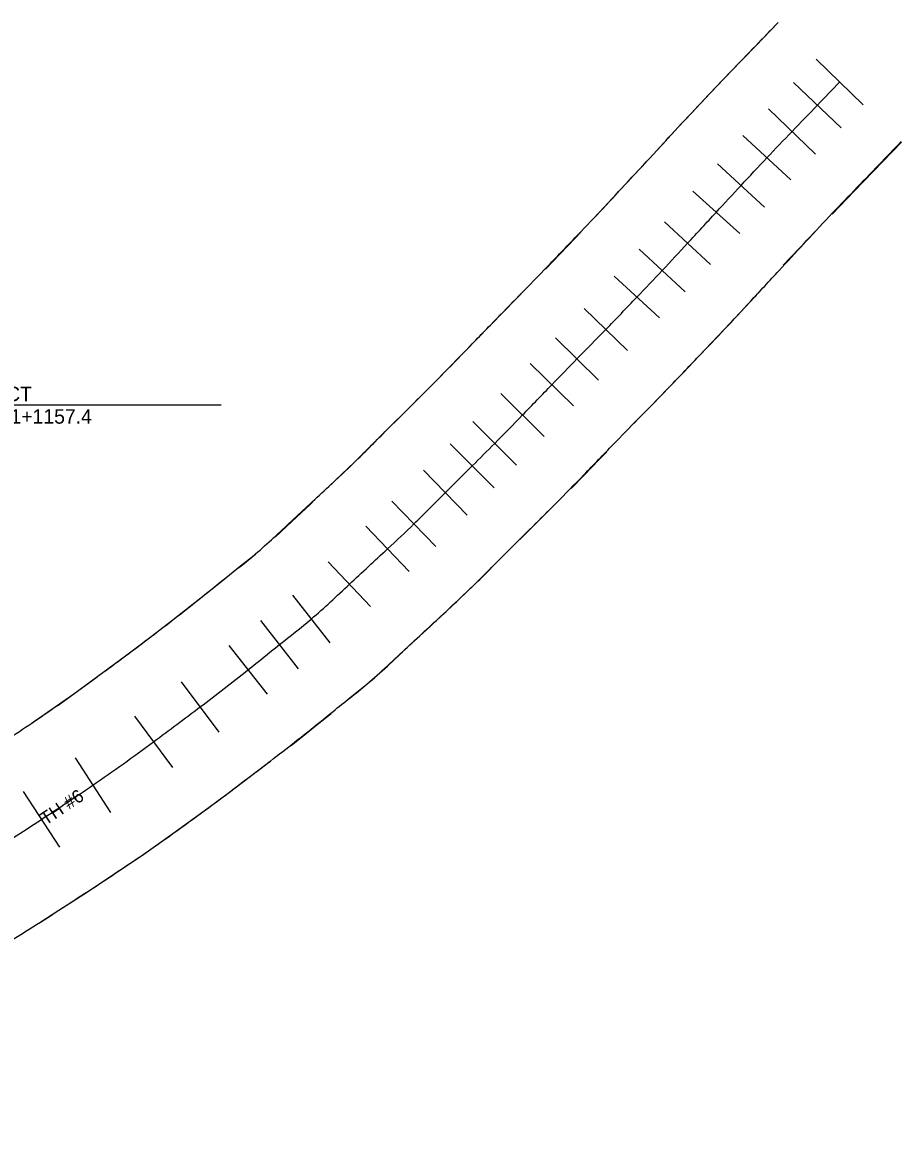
# Model space of a CAD drawing. Extents: x 435838 to 436160, y 121991 to 122158.
# Drawn here: x 436083.1 to 436160.1, y 122055.8 to 122154.8 of the extents above; entities that cross this region are included whole.
import ezdxf

# ---------------------------------------------------------------- set-up
doc = ezdxf.new("R2010")
doc.units = 0
for name, color, linetype in [('Level 1', 7, 'Continuous'), ('Level 10', 7, 'Continuous'), ('Level 12', 7, 'Continuous'), ('Level 5', 7, 'Continuous')]:
    doc.layers.add(name, color=color, linetype=linetype)

msp = doc.modelspace()

# ---------------------------------------------------------------- linework, layer by layer
at = {"layer": 'Level 1'}
for points in [[(436133.379, 122137.953), (436133.694, 122138.283), (436135.881, 122140.633), (436137.129, 122141.978), (436138.377, 122143.324), (436140.557, 122145.686), (436141.711, 122146.929), (436142.871, 122148.165), (436145.11, 122150.508), (436147.344, 122152.824), (436149.292, 122154.844)], [(436154.028, 122138.075), (436155.957, 122140.092), (436160.096, 122144.384)], [(436128.933, 122133.244), (436130.195, 122134.564), (436131.538, 122135.97), (436132.038, 122136.494)], [(436149.745, 122133.599), (436152.527, 122136.507)], [(436109.989, 122114.258), (436112.189, 122116.336), (436113.532, 122117.673), (436114.874, 122119.011), (436117.223, 122121.352), (436119.16, 122123.281), (436120.36, 122124.497), (436121.551, 122125.723), (436122.829, 122127.042), (436124.108, 122128.36), (436126.322, 122130.636), (436127.291, 122131.62)], [(436135.656, 122118.719), (436137.05, 122120.152), (436138.326, 122121.448), (436139.598, 122122.749), (436140.979, 122124.19), (436142.357, 122125.634), (436144.61, 122127.995), (436146.871, 122130.423), (436147.973, 122131.612)], [(436131.173, 122114.046), (436132.322, 122115.229), (436133.608, 122116.557), (436134.302, 122117.273)], [(436105.28, 122109.813), (436106.711, 122111.164), (436108.353, 122112.685), (436108.564, 122112.881)], [(436111.689, 122095.629), (436111.811, 122095.727), (436113.293, 122096.918), (436115.093, 122098.503), (436116.839, 122100.152), (436118.53, 122101.718), (436120.219, 122103.287), (436122.635, 122105.57), (436124.048, 122106.977), (436125.46, 122108.385), (436127.809, 122110.724), (436129.522, 122112.43)], [(436083.974, 122093.536), (436085.033, 122094.249), (436087.623, 122096.066), (436090.18, 122097.927), (436092.163, 122099.399), (436094.134, 122100.887), (436096.194, 122102.461), (436098.234, 122104.061), (436099.584, 122105.145), (436100.934, 122106.23), (436102.234, 122107.274), (436103.524, 122108.311)], [(436106.655, 122091.553), (436107.548, 122092.253), (436108.95, 122093.379), (436110.168, 122094.358)], [(436084.736, 122076.114), (436086.316, 122077.124), (436088.9, 122078.804), (436091.234, 122080.34), (436093.551, 122081.901), (436096.31, 122083.836), (436099.036, 122085.819), (436101.134, 122087.376), (436103.22, 122088.951), (436104.81, 122090.166)]]:
    msp.add_lwpolyline(points, dxfattribs=at)
for points in [[(436028.85, 122070.697), (436032.873, 122071.242), (436037.712, 122072.211), (436044.314, 122073.897), (436048.282, 122075.037), (436051.469, 122076.128), (436054.388, 122077.32), (436057.846, 122078.731), (436060.604, 122079.932), (436063.68, 122081.42), (436067.336, 122083.189), (436071.379, 122085.503), (436075.746, 122088.17), (436080.678, 122091.35), (436085.033, 122094.249), (436090.18, 122097.927), (436094.134, 122100.887), (436098.234, 122104.061), (436100.934, 122106.23), (436103.533, 122108.318), (436106.685, 122111.192), (436109.967, 122114.237), (436112.189, 122116.336), (436114.874, 122119.011), (436117.223, 122121.352), (436119.16, 122123.281), (436121.551, 122125.723), (436124.108, 122128.36), (436126.322, 122130.636), (436128.824, 122133.185), (436131.511, 122135.996), (436133.694, 122138.283), (436135.881, 122140.633), (436138.377, 122143.324), (436140.557, 122145.686), (436142.871, 122148.165), (436145.11, 122150.508), (436147.344, 122152.824), (436149.292, 122154.844)], [(436030.864, 122055.833), (436035.355, 122056.442), (436041.042, 122057.579), (436048.242, 122059.419), (436052.784, 122060.723), (436056.737, 122062.076), (436060.058, 122063.432), (436063.674, 122064.909), (436066.866, 122066.298), (436070.214, 122067.918), (436074.336, 122069.913), (436079.015, 122072.591), (436083.72, 122075.464), (436088.9, 122078.804), (436093.551, 122081.901), (436099.036, 122085.819), (436103.22, 122088.951), (436107.524, 122092.283), (436110.328, 122094.536), (436113.293, 122096.918), (436116.839, 122100.152), (436120.219, 122103.287), (436122.635, 122105.57), (436125.46, 122108.385), (436127.809, 122110.724), (436129.812, 122112.719), (436132.295, 122115.255), (436134.868, 122117.91), (436137.05, 122120.152), (436139.598, 122122.749), (436142.357, 122125.634), (436144.61, 122127.995), (436146.871, 122130.423), (436149.387, 122133.138), (436151.551, 122135.482), (436153.775, 122137.865), (436155.93, 122140.118), (436158.142, 122142.412), (436160.09, 122144.432)]]:
    msp.add_spline(points, degree=3, dxfattribs=at)
at = {"layer": 'Level 10'}
msp.add_line((436100.52, 122121.357), (436063.934, 122121.357), dxfattribs=at)
at = {"layer": 'Level 12'}
for p, q in [((436152.625, 122151.629), (436156.756, 122147.647)), ((436150.663, 122149.593), (436154.823, 122145.643)), ((436148.455, 122147.303), (436152.585, 122143.323)), ((436146.225, 122144.949), (436150.421, 122141.08)), ((436143.993, 122142.484), (436148.114, 122138.683)), ((436141.826, 122140.093), (436145.938, 122136.369)), ((436139.361, 122137.395), (436143.391, 122133.661)), ((436137.14, 122135.002), (436141.163, 122131.275)), ((436134.957, 122132.649), (436138.91, 122128.981)), ((436132.32, 122129.813), (436136.101, 122126.121)), ((436129.796, 122127.238), (436133.575, 122123.549)), ((436127.593, 122124.991), (436131.382, 122121.278)), ((436125.032, 122122.378), (436128.813, 122118.6)), ((436122.57, 122119.914), (436126.401, 122116.085)), ((436120.594, 122117.97), (436124.438, 122114.105)), ((436118.253, 122115.668), (436122.081, 122111.727)), ((436115.48, 122112.941), (436119.343, 122108.965)), ((436113.189, 122110.746), (436116.997, 122106.778)), ((436109.907, 122107.618), (436113.617, 122103.725)), ((436106.769, 122104.698), (436110.056, 122100.538)), ((436103.986, 122102.5), (436107.275, 122098.265)), ((436101.199, 122100.298), (436104.558, 122096.045)), ((436097.038, 122097.133), (436100.315, 122092.705)), ((436092.952, 122094.113), (436096.264, 122089.633)), ((436087.747, 122090.459), (436090.836, 122085.69)), ((436083.207, 122087.517), (436086.37, 122082.636))]:
    msp.add_line(p, q, dxfattribs=at)
msp.add_spline([(436029.857, 122063.265), (436034.114, 122063.842), (436039.377, 122064.895), (436046.278, 122066.658), (436050.533, 122067.88), (436054.103, 122069.102), (436057.223, 122070.376), (436060.76, 122071.82), (436063.735, 122073.115), (436066.947, 122074.669), (436070.836, 122076.551), (436075.197, 122079.047), (436079.733, 122081.817), (436084.789, 122085.077), (436089.292, 122088.075), (436094.608, 122091.873), (436098.677, 122094.919), (436102.879, 122098.172), (436105.631, 122100.383), (436108.413, 122102.618), (436111.762, 122105.672), (436115.093, 122108.762), (436117.412, 122110.953), (436120.167, 122113.698), (436122.516, 122116.038), (436124.486, 122118), (436126.923, 122120.489), (436129.488, 122123.135), (436131.686, 122125.394), (436134.211, 122127.967), (436136.934, 122130.815), (436139.152, 122133.139), (436141.376, 122135.528), (436143.882, 122138.231), (436146.054, 122140.584), (436148.323, 122143.015), (436150.52, 122145.313), (436152.743, 122147.618), (436154.691, 122149.638)], degree=3, dxfattribs=at)

# ---------------------------------------------------------------- texts
at = {"layer": 'Level 10'}
for s, p in [('END R.O.W. PROJECT', (436065.939, 122121.697)), ('BRO 1443 (32) STA. 1+1157.4', (436065.939, 122119.727))]:
    msp.add_text(s, height=1.270002, dxfattribs=at).set_placement(p)
at = {"layer": 'Level 5'}
msp.add_text('TH #6', height=1.142988, rotation=33.99999996, dxfattribs=at).set_placement((436085.174, 122084.52))

doc.saveas('drawing.dxf')
